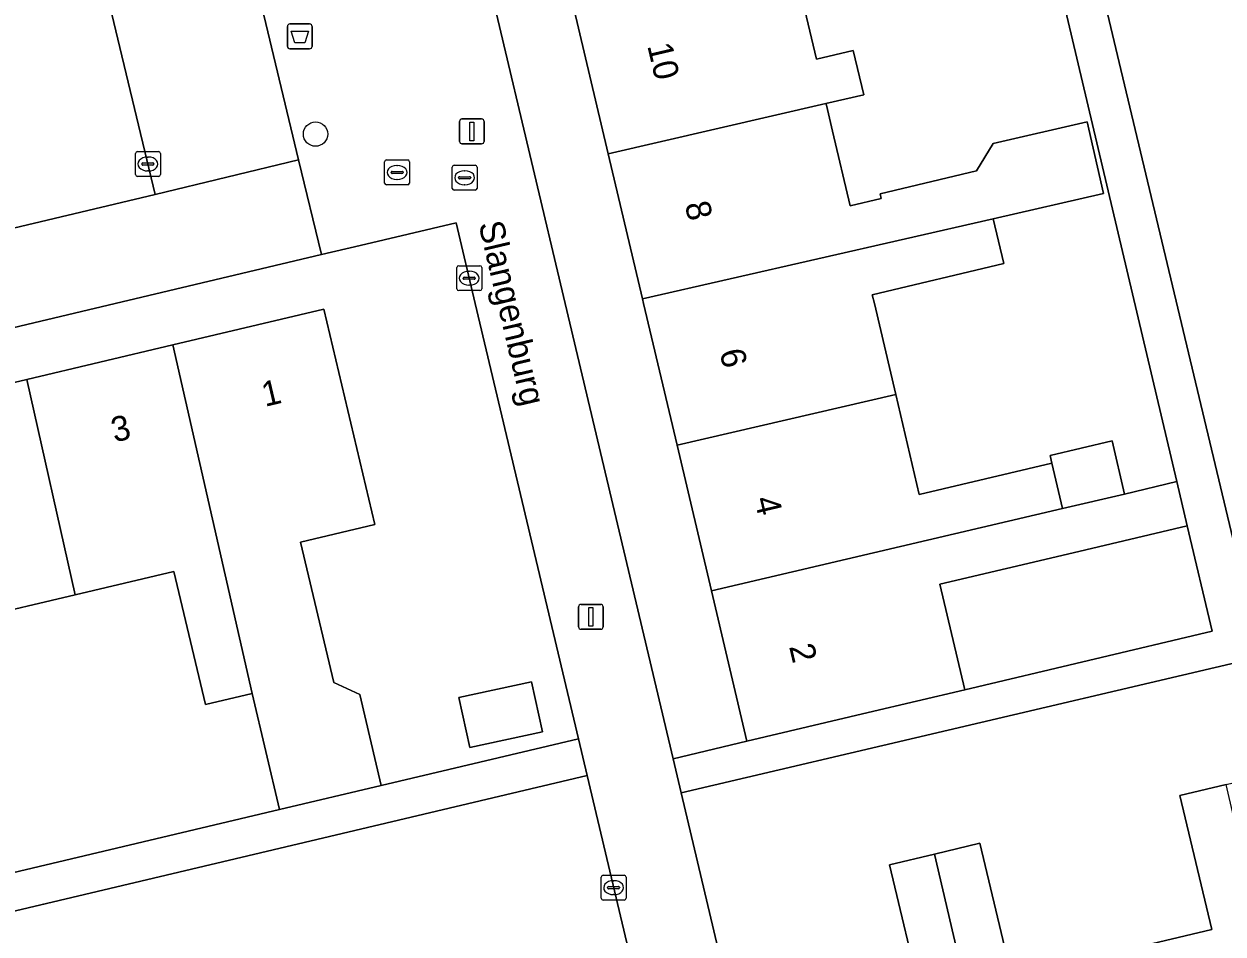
# Model space of a CAD drawing. Extents: x 158031 to 159244, y 380104 to 381214.
# Drawn here: x 158542.1 to 158590.29, y 380724.66 to 380761.24 of the extents above; entities that cross this region are included whole.
import ezdxf

# ---------------------------------------------------------------- set-up
doc = ezdxf.new("R2010")
doc.units = 0
for name, color, linetype in [('IMGEO_Afvalbak', 7, 'Continuous'), ('IMGEO_Boom', 7, 'Continuous'), ('IMGEO_Brandkraan', 7, 'Continuous'), ('IMGEO_Erf', 7, 'Continuous'), ('IMGEO_Kolk', 7, 'Continuous'), ('IMGEO_Lichtmast', 7, 'Continuous'), ('IMGEO_Openbare_ruimte_label', 7, 'Continuous'), ('IMGEO_Pand', 7, 'Continuous'), ('IMGEO_Pand_nummerreeks', 7, 'Continuous'), ('IMGEO_Parkeervlak_open', 7, 'Continuous'), ('IMGEO_Rijbaan_lokaal_open', 7, 'Continuous'), ('IMGEO_Rioolput', 7, 'Continuous'), ('IMGEO_Voetpad_open', 7, 'Continuous')]:
    doc.layers.add(name, color=color, linetype=linetype)

msp = doc.modelspace()

# ---------------------------------------------------------------- linework, layer by layer
at = {"layer": 'IMGEO_Afvalbak'}
for p, q in [((158552.789, 380761.24), (158553.579, 380761.24)), ((158553.579, 380761.24), (158552.789, 380761.24)), ((158552.689, 380760.34), (158552.689, 380761.14)), ((158552.689, 380761.14), (158552.689, 380760.34)), ((158553.679, 380761.14), (158553.679, 380760.34)), ((158553.679, 380760.34), (158553.679, 380761.14)), ((158553.579, 380760.24), (158552.789, 380760.24)), ((158552.789, 380760.24), (158553.579, 380760.24))]:
    msp.add_line(p, q, dxfattribs=at)
msp.add_lwpolyline([(158552.832, 380760.954), (158553.536, 380760.954), (158553.387, 380760.484), (158552.981, 380760.484), (158552.832, 380760.954)], dxfattribs=at)
for centre, start, end in [((158552.789, 380761.14), 90, 180), ((158552.789, 380761.14), 90, 180), ((158553.579, 380761.14), 0, 90), ((158553.579, 380761.14), 360, 90), ((158552.789, 380760.34), 180, 270), ((158552.789, 380760.34), 180, 270), ((158553.579, 380760.34), 270, 0), ((158553.579, 380760.34), 270, 0)]:
    msp.add_arc(centre, 0.1, start, end, dxfattribs=at)
at = {"layer": 'IMGEO_Boom'}
msp.add_circle((158553.817, 380756.813), 0.489, dxfattribs=at)
at = {"layer": 'IMGEO_Brandkraan'}
for p, q in [((158559.309, 380754.633), (158559.309, 380755.485)), ((158559.384, 380755.559), (158560.236, 380755.559)), ((158560.31, 380755.485), (158560.31, 380754.633)), ((158559.568, 380755.053), (158559.568, 380755.065)), ((158560.006, 380755.016), (158559.608, 380755.016)), ((158559.611, 380755.102), (158560.009, 380755.102)), ((158559.797, 380755.339), (158559.822, 380755.339)), ((158560.052, 380755.065), (158560.052, 380755.053)), ((158560.236, 380754.559), (158559.384, 380754.559)), ((158559.82, 380754.779), (158559.795, 380754.779))]:
    msp.add_line(p, q, dxfattribs=at)
for points in [[(158559.309, 380754.633), (158559.309, 380755.485)], [(158559.384, 380755.559), (158560.236, 380755.559)], [(158560.31, 380755.485), (158560.31, 380754.633)], [(158560.236, 380754.559), (158559.384, 380754.559)]]:
    msp.add_lwpolyline(points, dxfattribs=at)
for centre, radius, start, end in [((158559.386, 380755.483), 0.0765, 91.552, 178.448), ((158559.386, 380755.483), 0.0765, 91.552, 178.448), ((158560.234, 380755.483), 0.0765, 1.552, 88.448), ((158560.234, 380755.483), 0.0765, 1.552, 88.448), ((158559.608, 380755.062), 0.0403, 85.8775, 175.7526), ((158559.605, 380755.052), 0.0366, 178.938, 274.7102), ((158560.009, 380755.059), 0.043, 264.8664, 352.4533), ((158560.013, 380755.064), 0.0386, 1.7309, 96.639), ((158559.386, 380754.635), 0.0765, 181.552, 268.448), ((158559.386, 380754.635), 0.0765, 181.552, 268.448), ((158560.234, 380754.635), 0.0765, 271.552, 358.448), ((158560.234, 380754.635), 0.0765, 271.552, 358.448)]:
    msp.add_arc(centre, radius, start, end, dxfattribs=at)
for centre, major_axis, ratio, start_param, end_param in [((158559.796, 380755.059), (-0.387, 0.002), 0.722429, 4.712389, 7.853982), ((158559.821, 380755.059), (-0.39, 0.002), 0.717154, 1.570796, 4.712389)]:
    msp.add_ellipse(centre, major_axis=major_axis, ratio=ratio, start_param=start_param, end_param=end_param, dxfattribs=at)
at = {"layer": 'IMGEO_Erf'}
for points in [[(158598.899, 380750), (158598.561, 380751.427), (158597.627, 380755.367), (158592.275, 380754.116), (158591.833, 380756.006), (158591.411, 380757.814), (158596.728, 380759.056), (158595.788, 380763.076), (158594.324, 380762.734), (158593.901, 380764.544), (158592.892, 380768.863), (158590.165, 380768.213), (158587.286, 380767.526), (158584.406, 380766.84), (158586.112, 380759.687), (158591.465, 380737.246), (158601.276, 380739.54), (158600.309, 380743.68), (158595.041, 380742.448), (158594.593, 380744.364), (158594.166, 380746.188), (158599.506, 380747.436)], [(158568.345, 380744.309), (158567.002, 380750), (158566.957, 380750.189), (158565.582, 380756.016), (158564.16, 380762.039), (158565.133, 380762.27), (158563.743, 380768.102), (158559.795, 380767.141), (158563.854, 380750), (158568.185, 380731.708), (158571.154, 380732.409), (158569.726, 380738.457)], [(158588.845, 380741.072), (158584.257, 380739.988), (158578.904, 380738.721), (158579.907, 380734.482), (158589.846, 380736.837)], [(158560.014, 380732.159), (158559.576, 380734.169), (158562.494, 380734.805), (158562.932, 380732.795)]]:
    msp.add_lwpolyline(points, close=True, dxfattribs=at)
for points in [[(158572.935, 380764.117), (158573.95, 380759.83), (158575.422, 380760.179), (158575.845, 380758.393), (158574.328, 380758.042), (158574.344, 380757.975), (158574.59, 380756.936), (158575.302, 380753.93), (158576.546, 380754.225), (158576.501, 380754.413), (158580.382, 380755.332), (158581.049, 380756.438), (158584.821, 380757.301), (158585.478, 380754.426), (158581.053, 380753.414), (158581.48, 380751.611), (158576.192, 380750.358), (158576.276, 380750), (158577.131, 380746.349), (158578.072, 380742.332), (158583.404, 380743.594), (158583.334, 380743.891), (158585.824, 380744.481), (158586.328, 380742.349), (158588.426, 380742.845), (158582.853, 380766.459)], [(158536.368, 380745.569), (158542.212, 380746.953), (158548.086, 380748.344), (158554.154, 380749.781), (158556.205, 380741.118), (158553.218, 380740.411), (158554.554, 380734.767), (158555.592, 380734.295), (158556.459, 380730.636), (158564.379, 380732.511), (158560.236, 380750), (158559.465, 380753.253), (158555.616, 380752.341), (158554.051, 380751.969), (158545.767, 380750), (158515.725, 380742.86)], [(158526.203, 380723.472), (158552.37, 380729.668), (158551.265, 380734.335), (158549.395, 380733.892), (158548.128, 380739.241), (158544.152, 380738.299), (158540.055, 380737.329)], [(158588.547, 380730.227), (158590.405, 380730.671), (158592.215, 380731.104), (158593.505, 380725.71), (158597.522, 380726.67), (158596.722, 380730.128), (158600.454, 380731.021), (158599.987, 380733.015), (158599.363, 380735.675), (158601.129, 380736.089), (158600.705, 380737.896), (158568.508, 380730.343), (158573.761, 380708.16), (158615.556, 380718.152)], [(158500, 380690.536), (158567.068, 380706.513), (158570.352, 380707.295), (158564.728, 380731.038), (158521.04, 380720.689)], [(158585.83, 380723.889), (158589.833, 380724.846), (158588.547, 380730.227)], [(158578.181, 380722.003), (158576.88, 380727.444), (158578.685, 380727.875), (158580.508, 380728.311), (158581.795, 380722.925)]]:
    msp.add_lwpolyline(points, dxfattribs=at)
at = {"layer": 'IMGEO_Kolk'}
for p, q in [((158546.581, 380755.186), (158546.581, 380756.038)), ((158546.656, 380756.112), (158547.508, 380756.112)), ((158547.069, 380755.892), (158547.094, 380755.892)), ((158547.582, 380756.038), (158547.582, 380755.186)), ((158546.84, 380755.606), (158546.84, 380755.618)), ((158547.278, 380755.569), (158546.88, 380755.569)), ((158546.883, 380755.655), (158547.281, 380755.655)), ((158547.324, 380755.618), (158547.324, 380755.606)), ((158547.508, 380755.112), (158546.656, 380755.112)), ((158547.092, 380755.332), (158547.067, 380755.332)), ((158559.569, 380751.522), (158560.421, 380751.522)), ((158559.494, 380750.596), (158559.494, 380751.448)), ((158559.753, 380751.016), (158559.753, 380751.028)), ((158559.796, 380751.065), (158560.194, 380751.065)), ((158559.982, 380751.302), (158560.007, 380751.302)), ((158560.237, 380751.028), (158560.237, 380751.016)), ((158560.495, 380751.448), (158560.495, 380750.596)), ((158560.191, 380750.979), (158559.793, 380750.979)), ((158560.005, 380750.742), (158559.98, 380750.742)), ((158560.421, 380750.522), (158559.569, 380750.522)), ((158565.296, 380726.102), (158565.296, 380726.954)), ((158565.371, 380727.028), (158566.223, 380727.028)), ((158566.297, 380726.954), (158566.297, 380726.102)), ((158565.555, 380726.522), (158565.555, 380726.534)), ((158565.993, 380726.485), (158565.595, 380726.485)), ((158565.598, 380726.571), (158565.996, 380726.571)), ((158565.784, 380726.808), (158565.809, 380726.808)), ((158566.039, 380726.534), (158566.039, 380726.522)), ((158566.223, 380726.028), (158565.371, 380726.028)), ((158565.807, 380726.248), (158565.782, 380726.248))]:
    msp.add_line(p, q, dxfattribs=at)
for points in [[(158546.581, 380755.186), (158546.581, 380756.038)], [(158546.656, 380756.112), (158547.508, 380756.112)], [(158547.582, 380756.038), (158547.582, 380755.186)], [(158547.508, 380755.112), (158546.656, 380755.112)], [(158559.569, 380751.522), (158560.421, 380751.522)], [(158559.494, 380750.596), (158559.494, 380751.448)], [(158560.495, 380751.448), (158560.495, 380750.596)], [(158560.421, 380750.522), (158559.569, 380750.522)], [(158565.296, 380726.102), (158565.296, 380726.954)], [(158565.371, 380727.028), (158566.223, 380727.028)], [(158566.297, 380726.954), (158566.297, 380726.102)], [(158566.223, 380726.028), (158565.371, 380726.028)]]:
    msp.add_lwpolyline(points, dxfattribs=at)
for centre, radius, start, end in [((158546.658, 380756.036), 0.0765, 91.552, 178.448), ((158546.658, 380756.036), 0.0765, 91.552, 178.448), ((158547.506, 380756.036), 0.0765, 1.552, 88.448), ((158547.506, 380756.036), 0.0765, 1.552, 88.448), ((158546.88, 380755.615), 0.0403, 85.8775, 175.7526), ((158546.877, 380755.605), 0.0366, 178.938, 274.7102), ((158547.281, 380755.612), 0.043, 264.8664, 352.4533), ((158547.285, 380755.617), 0.0386, 1.7309, 96.639), ((158546.658, 380755.188), 0.0765, 181.552, 268.448), ((158546.658, 380755.188), 0.0765, 181.552, 268.448), ((158547.506, 380755.188), 0.0765, 271.552, 358.448), ((158547.506, 380755.188), 0.0765, 271.552, 358.448), ((158559.571, 380751.446), 0.0765, 91.552, 178.448), ((158559.571, 380751.446), 0.0765, 91.552, 178.448), ((158560.419, 380751.446), 0.0765, 1.552, 88.448), ((158560.419, 380751.446), 0.0765, 1.552, 88.448), ((158559.793, 380751.025), 0.0403, 85.8775, 175.7526), ((158560.198, 380751.027), 0.0386, 1.7309, 96.639), ((158559.571, 380750.598), 0.0765, 181.552, 268.448), ((158559.571, 380750.598), 0.0765, 181.552, 268.448), ((158559.79, 380751.015), 0.0366, 178.938, 274.7102), ((158560.194, 380751.022), 0.043, 264.8664, 352.4533), ((158560.419, 380750.598), 0.0765, 271.552, 358.448), ((158560.419, 380750.598), 0.0765, 271.552, 358.448), ((158565.373, 380726.952), 0.0765, 91.552, 178.448), ((158565.373, 380726.952), 0.0765, 91.552, 178.448), ((158566.221, 380726.952), 0.0765, 1.552, 88.448), ((158566.221, 380726.952), 0.0765, 1.552, 88.448), ((158565.595, 380726.531), 0.0403, 85.8775, 175.7526), ((158565.592, 380726.521), 0.0366, 178.938, 274.7102), ((158565.996, 380726.528), 0.043, 264.8664, 352.4533), ((158566, 380726.533), 0.0386, 1.7309, 96.639), ((158565.373, 380726.104), 0.0765, 181.552, 268.448), ((158565.373, 380726.104), 0.0765, 181.552, 268.448), ((158566.221, 380726.104), 0.0765, 271.552, 358.448), ((158566.221, 380726.104), 0.0765, 271.552, 358.448)]:
    msp.add_arc(centre, radius, start, end, dxfattribs=at)
for centre, major_axis, ratio, start_param, end_param in [((158547.068, 380755.612), (-0.387, 0.002), 0.722429, 4.712389, 7.853982), ((158547.093, 380755.612), (-0.39, 0.002), 0.717154, 1.570796, 4.712389), ((158559.981, 380751.022), (-0.387, 0.002), 0.722429, 4.712389, 7.853982), ((158560.006, 380751.022), (-0.39, 0.002), 0.717154, 1.570796, 4.712389), ((158565.783, 380726.528), (-0.387, 0.002), 0.722429, 4.712389, 7.853982), ((158565.808, 380726.528), (-0.39, 0.002), 0.717154, 1.570796, 4.712389)]:
    msp.add_ellipse(centre, major_axis=major_axis, ratio=ratio, start_param=start_param, end_param=end_param, dxfattribs=at)
at = {"layer": 'IMGEO_Lichtmast'}
for p, q in [((158559.602, 380756.522), (158559.602, 380757.322)), ((158559.602, 380757.322), (158559.602, 380756.522)), ((158559.702, 380757.422), (158560.492, 380757.422)), ((158560.492, 380757.422), (158559.702, 380757.422)), ((158560.592, 380757.322), (158560.592, 380756.522)), ((158560.592, 380756.522), (158560.592, 380757.322)), ((158560.492, 380756.422), (158559.702, 380756.422)), ((158559.702, 380756.422), (158560.492, 380756.422)), ((158564.386, 380737.012), (158564.386, 380737.812)), ((158564.386, 380737.812), (158564.386, 380737.012)), ((158564.486, 380737.912), (158565.276, 380737.912)), ((158565.276, 380737.912), (158564.486, 380737.912)), ((158565.376, 380737.812), (158565.376, 380737.012)), ((158565.376, 380737.012), (158565.376, 380737.812)), ((158565.276, 380736.912), (158564.486, 380736.912)), ((158564.486, 380736.912), (158565.276, 380736.912))]:
    msp.add_line(p, q, dxfattribs=at)
for points in [[(158560.022, 380757.297), (158560.172, 380757.297), (158560.172, 380756.547), (158560.022, 380756.547), (158560.022, 380757.297)], [(158564.806, 380737.787), (158564.956, 380737.787), (158564.956, 380737.037), (158564.806, 380737.037), (158564.806, 380737.787)]]:
    msp.add_lwpolyline(points, dxfattribs=at)
for centre, start, end in [((158559.702, 380757.322), 90, 180), ((158559.702, 380757.322), 90, 180), ((158560.492, 380757.322), 0, 90), ((158560.492, 380757.322), 360, 90), ((158559.702, 380756.522), 180, 270), ((158559.702, 380756.522), 180, 270), ((158560.492, 380756.522), 270, 0), ((158560.492, 380756.522), 270, 0), ((158564.486, 380737.812), 90, 180), ((158564.486, 380737.812), 90, 180), ((158565.276, 380737.812), 0, 90), ((158565.276, 380737.812), 360, 90), ((158564.486, 380737.012), 180, 270), ((158564.486, 380737.012), 180, 270), ((158565.276, 380737.012), 270, 0), ((158565.276, 380737.012), 270, 0)]:
    msp.add_arc(centre, 0.1, start, end, dxfattribs=at)
at = {"layer": 'IMGEO_Pand'}
for points in [[(158572.935, 380764.117), (158571.04, 380763.668), (158568.087, 380762.969), (158565.133, 380762.27), (158564.16, 380762.039), (158565.582, 380756.016), (158574.328, 380758.042), (158575.845, 380758.393), (158575.422, 380760.179), (158573.95, 380759.83)], [(158574.328, 380758.042), (158565.582, 380756.016), (158566.957, 380750.189), (158581.053, 380753.414), (158585.478, 380754.426), (158584.821, 380757.301), (158581.049, 380756.438), (158580.382, 380755.332), (158576.501, 380754.413), (158576.546, 380754.225), (158575.302, 380753.93), (158574.59, 380756.936), (158574.344, 380757.975)], [(158566.957, 380750.189), (158567.002, 380750), (158568.345, 380744.309), (158577.131, 380746.349), (158576.276, 380750), (158576.192, 380750.358), (158581.48, 380751.611), (158581.053, 380753.414)], [(158551.265, 380734.335), (158552.37, 380729.668), (158556.459, 380730.636), (158555.592, 380734.295), (158554.554, 380734.767), (158553.218, 380740.411), (158556.205, 380741.118), (158554.154, 380749.781), (158548.086, 380748.344)], [(158551.265, 380734.335), (158548.086, 380748.344), (158542.212, 380746.953), (158544.152, 380738.299), (158548.128, 380739.241), (158549.395, 380733.892)], [(158536.368, 380745.569), (158539.599, 380731.57), (158541.322, 380731.978), (158540.055, 380737.329), (158544.152, 380738.299), (158542.212, 380746.953)], [(158583.838, 380741.761), (158583.404, 380743.594), (158578.072, 380742.332), (158577.131, 380746.349), (158568.345, 380744.309), (158569.726, 380738.457)], [(158583.404, 380743.594), (158583.838, 380741.761), (158586.328, 380742.349), (158585.824, 380744.481), (158583.334, 380743.891)], [(158588.845, 380741.072), (158588.426, 380742.845), (158586.328, 380742.349), (158583.838, 380741.761), (158569.726, 380738.457), (158571.154, 380732.409), (158576.02, 380733.561), (158579.907, 380734.482), (158578.904, 380738.721), (158584.257, 380739.988)], [(158559.576, 380734.169), (158560.014, 380732.159), (158562.932, 380732.795), (158562.494, 380734.805)], [(158590.405, 380730.671), (158588.547, 380730.227), (158589.833, 380724.846), (158585.83, 380723.889), (158587.833, 380715.163), (158593.675, 380716.56)], [(158581.991, 380713.766), (158587.833, 380715.163), (158585.83, 380723.889), (158581.795, 380722.925), (158580.508, 380728.311), (158578.685, 380727.875)], [(158578.685, 380727.875), (158576.88, 380727.444), (158578.181, 380722.003), (158573.855, 380720.969), (158575.924, 380712.316), (158581.991, 380713.766)]]:
    msp.add_lwpolyline(points, close=True, dxfattribs=at)
at = {"layer": 'IMGEO_Parkeervlak_open'}
msp.add_lwpolyline([(158547.375, 380754.387), (158553.139, 380755.776), (158550.898, 380765.127), (158545.124, 380763.759)], close=True, dxfattribs=at)
at = {"layer": 'IMGEO_Rijbaan_lokaal_open'}
msp.add_lwpolyline([(158541.806, 380778.346), (158538.573, 380791.773), (158538.226, 380793.212), (158538.129, 380793.613), (158535.941, 380793.094), (158520.821, 380789.512), (158516.767, 380788.551), (158525.714, 380750), (158525.882, 380749.276), (158528.927, 380750), (158547.375, 380754.387), (158545.124, 380763.759), (158544.131, 380767.891), (158542.939, 380773.643)], close=True, dxfattribs=at)
at = {"layer": 'IMGEO_Rioolput'}
for p, q in [((158556.593, 380754.848), (158556.593, 380755.7)), ((158556.668, 380755.774), (158557.52, 380755.774)), ((158557.081, 380755.554), (158557.106, 380755.554)), ((158557.594, 380755.7), (158557.594, 380754.848)), ((158556.852, 380755.268), (158556.852, 380755.28)), ((158557.29, 380755.231), (158556.892, 380755.231)), ((158556.895, 380755.317), (158557.293, 380755.317)), ((158557.104, 380754.994), (158557.079, 380754.994)), ((158557.336, 380755.28), (158557.336, 380755.268)), ((158557.52, 380754.774), (158556.668, 380754.774))]:
    msp.add_line(p, q, dxfattribs=at)
for points in [[(158556.593, 380754.848), (158556.593, 380755.7)], [(158556.668, 380755.774), (158557.52, 380755.774)], [(158557.594, 380755.7), (158557.594, 380754.848)], [(158557.52, 380754.774), (158556.668, 380754.774)]]:
    msp.add_lwpolyline(points, dxfattribs=at)
for centre, radius, start, end in [((158556.67, 380755.698), 0.0765, 91.552, 178.448), ((158556.67, 380755.698), 0.0765, 91.552, 178.448), ((158557.518, 380755.698), 0.0765, 1.552, 88.448), ((158557.518, 380755.698), 0.0765, 1.552, 88.448), ((158556.892, 380755.277), 0.0403, 85.8775, 175.7526), ((158556.889, 380755.267), 0.0366, 178.938, 274.7102), ((158557.293, 380755.274), 0.043, 264.8664, 352.4533), ((158557.297, 380755.279), 0.0386, 1.7309, 96.639), ((158556.67, 380754.85), 0.0765, 181.552, 268.448), ((158556.67, 380754.85), 0.0765, 181.552, 268.448), ((158557.518, 380754.85), 0.0765, 271.552, 358.448), ((158557.518, 380754.85), 0.0765, 271.552, 358.448)]:
    msp.add_arc(centre, radius, start, end, dxfattribs=at)
for centre, major_axis, ratio, start_param, end_param in [((158557.08, 380755.274), (-0.387, 0.002), 0.722429, 4.712389, 7.853982), ((158557.105, 380755.274), (-0.39, 0.002), 0.717154, 1.570796, 4.712389)]:
    msp.add_ellipse(centre, major_axis=major_axis, ratio=ratio, start_param=start_param, end_param=end_param, dxfattribs=at)
at = {"layer": 'IMGEO_Voetpad_open'}
for points in [[(158600.705, 380737.896), (158606.84, 380739.335), (158612.318, 380740.656), (158611.977, 380742.07), (158609.955, 380741.569), (158605.087, 380740.431), (158601.276, 380739.54), (158591.465, 380737.246), (158586.112, 380759.687), (158584.406, 380766.84), (158583.009, 380772.697), (158581.455, 380772.326), (158582.853, 380766.459), (158588.426, 380742.845), (158588.845, 380741.072), (158589.846, 380736.837), (158579.907, 380734.482), (158576.02, 380733.561), (158571.154, 380732.409), (158568.185, 380731.708), (158568.508, 380730.343)], [(158559.795, 380767.141), (158550.898, 380765.127), (158553.139, 380755.776), (158554.051, 380751.969), (158555.616, 380752.341), (158559.465, 380753.253), (158560.236, 380750), (158564.379, 380732.511), (158564.728, 380731.038), (158570.352, 380707.295), (158573.761, 380708.16), (158568.508, 380730.343), (158568.185, 380731.708), (158563.854, 380750)], [(158515.725, 380742.86), (158514.435, 380742.553), (158514.382, 380742.54), (158515.307, 380738.636), (158516.459, 380733.771), (158517.376, 380729.899), (158519.715, 380720.024), (158478.688, 380710.278), (158472.622, 380708.837), (158472.966, 380707.473), (158479.132, 380708.938), (158480.571, 380709.28), (158521.442, 380718.991), (158521.04, 380720.689), (158564.728, 380731.038), (158564.379, 380732.511), (158556.459, 380730.636), (158552.37, 380729.668), (158526.203, 380723.472), (158520.628, 380722.152)]]:
    msp.add_lwpolyline(points, close=True, dxfattribs=at)
msp.add_lwpolyline([(158464.494, 380730.142), (158468.687, 380731.665), (158468.822, 380731.711), (158468.961, 380731.745), (158500, 380739.122), (158514.382, 380742.54), (158514.435, 380742.553), (158515.725, 380742.86), (158545.767, 380750), (158554.051, 380751.969), (158553.139, 380755.776), (158547.375, 380754.387), (158528.927, 380750), (158525.882, 380749.276), (158522.019, 380748.055), (158513.376, 380745.986), (158501.421, 380743.123), (158500, 380742.783), (158499.62, 380742.692), (158478.792, 380737.705), (158478.748, 380737.696), (158478.584, 380737.674), (158474.565, 380737.039), (158458.956, 380733.307)], dxfattribs=at)

# ---------------------------------------------------------------- texts
at = {"layer": 'IMGEO_Openbare_ruimte_label'}
msp.add_text('Slangenburg', height=1, rotation=283.2996, dxfattribs=at).set_placement((158560.361, 380753.201))
at = {"layer": 'IMGEO_Pand_nummerreeks'}
for s, rotation, p in [('10', 283.281, (158567.144, 380760.367)), ('8', 283.281, (158568.649, 380753.993)), ('6', 283.2812, (158570.046, 380748.071)), ('1', 13.3236, (158551.785, 380745.849)), ('3', 13.3236, (158545.738, 380744.417)), ('4', 283.2812, (158571.445, 380742.145)), ('2', 283.281, (158572.844, 380736.221))]:
    msp.add_text(s, height=1, rotation=rotation, dxfattribs=at).set_placement(p)

doc.saveas('drawing.dxf')
